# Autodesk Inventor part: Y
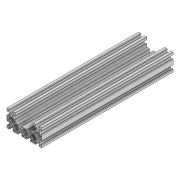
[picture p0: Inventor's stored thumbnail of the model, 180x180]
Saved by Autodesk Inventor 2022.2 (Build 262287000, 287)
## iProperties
Created: 2024-09
Part Number: Y
Material: Generico
Document SubType Name: Modeling
Designer: 18907419
Density: 1 g/cm^3
Appearance: Default
Author: 18907419
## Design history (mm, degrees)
sketch "Schizzo1"
  geometry: L1 (29.79, -3.9)-(30, -3.69); L2 (30, -3.69)-(30.21, -3.9); L3 (30.21, -3.9)-(32.839, -3.9); L4 (32.839, -3.9)-(35.5, -6.561); L5 (35.5, -6.561)-(35.5, -8.2); L6 (35.5, -8.2)-(33.395, -8.2); L7 (33.395, -8.2)-(33.395, -8.815); L8 (33.395, -8.815)-(34.58, -10); L9 (34.58, -10)-(39.5, -10); L10 (40, -9.5)-(40, -4.58); L11 (40, -4.58)-(38.815, -3.395); L12 (38.815, -3.395)-(38.2, -3.395); L13 (38.2, -3.395)-(38.2, -5.5); L14 (38.2, -5.5)-(36.561, -5.5); L15 (36.561, -5.5)-(33.9, -2.839); L16 (33.9, -2.839)-(33.9, -0.21); L17 (33.9, -0.21)-(33.69, 0); L18 (33.69, 0)-(33.9, 0.21); L19 (33.9, 0.21)-(33.9, 2.839); L20 (33.9, 2.839)-(36.561, 5.5); L21 (36.561, 5.5)-(38.2, 5.5); L22 (38.2, 5.5)-(38.2, 3.395); L23 (38.2, 3.395)-(38.815, 3.395); L24 (38.815, 3.395)-(40, 4.58); L25 (40, 4.58)-(40, 15.42); L26 (40, 15.42)-(38.815, 16.605); L27 (38.815, 16.605)-(38.2, 16.605); L28 (38.2, 16.605)-(38.2, 14.5); L29 (38.2, 14.5)-(36.561, 14.5); L30 (36.561, 14.5)-(33.9, 17.161); L31 (33.9, 17.161)-(33.9, 19.79); L32 (33.9, 19.79)-(33.69, 20); L33 (33.69, 20)-(33.9, 20.21); L34 (33.9, 20.21)-(33.9, 22.839); L35 (33.9, 22.839)-(36.561, 25.5); L36 (36.561, 25.5)-(38.2, 25.5); L37 (38.2, 25.5)-(38.2, 23.395); L38 (38.2, 23.395)-(38.815, 23.395); L39 (38.815, 23.395)-(40, 24.58); L40 (40, 24.58)-(40, 29.5); L41 (39.5, 30)-(34.58, 30); L42 (34.58, 30)-(33.395, 28.815); L43 (33.395, 28.815)-(33.395, 28.2); L44 (33.395, 28.2)-(35.5, 28.2); L45 (35.5, 28.2)-(35.5, 26.561); L46 (35.5, 26.561)-(32.839, 23.9); L47 (32.839, 23.9)-(30.21, 23.9); L48 (30.21, 23.9)-(30, 23.69); L49 (30, 23.69)-(29.79, 23.9); L50 (29.79, 23.9)-(27.161, 23.9); L51 (27.161, 23.9)-(24.5, 26.561); L52 (24.5, 26.561)-(24.5, 28.2); L53 (24.5, 28.2)-(26.605, 28.2); L54 (26.605, 28.2)-(26.605, 28.815); L55 (26.605, 28.815)-(25.42, 30); L56 (25.42, 30)-(20.5, 30); L57 (20, 29.5)-(20, 24.58); L58 (20, 24.58)-(21.185, 23.395); L59 (21.185, 23.395)-(21.8, 23.395); L60 (21.8, 23.395)-(21.8, 25.5); L61 (21.8, 25.5)-(23.439, 25.5); L62 (23.439, 25.5)-(26.1, 22.839); L63 (26.1, 22.839)-(26.1, 20.21); L64 (26.1, 20.21)-(26.31, 20)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; C1 r 2.3 at (-30, 0); C2 r 2.3 at (-30, 20); C3 r 2.3 at (-10, 0); C4 r 2.3 at (10, 0); C5 r 2.3 at (30, 0); C6 r 2.3 at (30, 20); A1 r 0.5 centre (39.5, -9.5) between (39.5, -10) and (40, -9.5); A2 r 0.5 centre (39.5, 29.5) between (40, 29.5) and (39.5, 30); A3 r 0.5 centre (20.5, 29.5) between (20.5, 30) and (20, 29.5); A4 r 0.5 centre (-20.5, 29.5) between (-20, 29.5) and (-20.5, 30); A5 r 0.5 centre (-39.5, 29.5) between (-39.5, 30) and (-40, 29.5); A6 r 0.5 centre (-39.5, -9.5) between (-40, -9.5) and (-39.5, -10); 311 further points
  constraints: 608 end point, 12 centre point, 12 point on circle
extrude "Estrusione1" new body sketch "Schizzo1" distance "d0" = 300; taper "d1" = 0 deg
node "Solido1"
